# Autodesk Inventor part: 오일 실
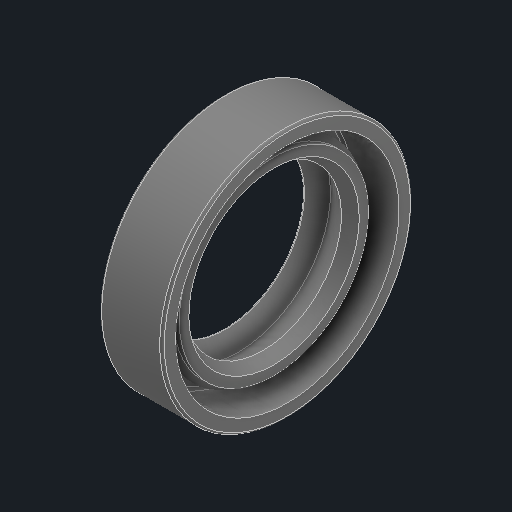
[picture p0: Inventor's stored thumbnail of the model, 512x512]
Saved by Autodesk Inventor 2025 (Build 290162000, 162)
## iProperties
Created: 2025-08
Part Number: 오일 실
Material: 고무
Description: 오일-실
Document SubType Name: Modeling
Designer: infra17
Density: 0.93 g/cm^3
Appearance: 기본값
Author: jhkim
Sending System: Autodesk Inventor 2026
Preprocessor: ST-DEVELOPER v20.1
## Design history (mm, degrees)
feature "Solid1"
node "솔리드1"
